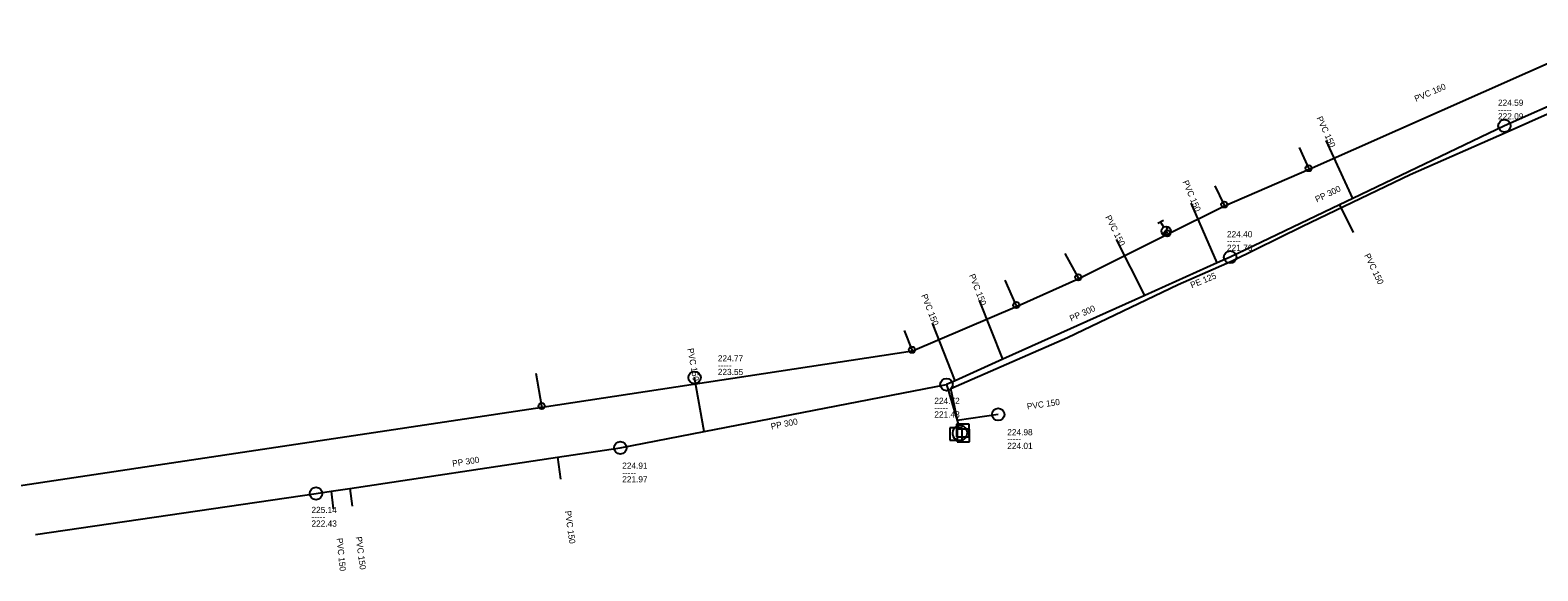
# Model space of a CAD drawing. Extents: x -770828 to -770111, y -1050344 to -1049447.
# Drawn here: x -770523.9 to -770280.9, y -1050344.4 to -1050257.2 of the extents above; entities that cross this region are included whole.
import ezdxf

# ---------------------------------------------------------------- set-up
doc = ezdxf.new("R2010")
doc.units = 0
doc.layers.add('Level 0', color=7, linetype='Continuous')

msp = doc.modelspace()

# ---------------------------------------------------------------- linework, layer by layer
at = {"layer": 'Level 0'}
for p, q in [((-770267.13, -1050257.23), (-770317.71, -1050279.72)), ((-770264.95, -1050263.2), (-770286.27, -1050272.66)), ((-770285.81, -1050273.65), (-770264.35, -1050264)), ((-770286.27, -1050272.66), (-770310.7, -1050284.36)), ((-770301.46, -1050280.51), (-770285.81, -1050273.65)), ((-770317.81, -1050279.5), (-770319.29, -1050276.15)), ((-770310.7, -1050284.36), (-770315.01, -1050275.04)), ((-770317.71, -1050279.72), (-770317.81, -1050279.5)), ((-770317.71, -1050279.72), (-770331.38, -1050285.6)), ((-770318.79, -1050288.84), (-770301.46, -1050280.51)), ((-770331.42, -1050285.36), (-770332.9, -1050282.35)), ((-770310.7, -1050284.36), (-770312.83, -1050285.38)), ((-770331.38, -1050285.6), (-770340.54, -1050290.17)), ((-770332.58, -1050294.78), (-770336.74, -1050285.12)), ((-770331.38, -1050285.6), (-770331.42, -1050285.36)), ((-770312.83, -1050285.38), (-770330.47, -1050293.83)), ((-770312.83, -1050285.38), (-770310.66, -1050289.87)), ((-770342.1, -1050288.37), (-770341.23, -1050287.87)), ((-770341.17, -1050288.99), (-770341.67, -1050288.12)), ((-770341.07, -1050290.33), (-770340.51, -1050288.94)), ((-770330.16, -1050294.43), (-770318.79, -1050288.84)), ((-770340.54, -1050290.17), (-770354.88, -1050297.33)), ((-770344.21, -1050300.01), (-770348.78, -1050291)), ((-770340.79, -1050289.64), (-770340.61, -1050290)), ((-770340.61, -1050290), (-770340.54, -1050290.17)), ((-770354.94, -1050297.09), (-770357.06, -1050293.23)), ((-770330.47, -1050293.83), (-770332.58, -1050294.78)), ((-770332.58, -1050294.78), (-770344.21, -1050300.01)), ((-770338.86, -1050298.24), (-770330.16, -1050294.43)), ((-770364.93, -1050301.57), (-770366.74, -1050297.55)), ((-770354.88, -1050297.33), (-770364.81, -1050301.79)), ((-770356.68, -1050306.8), (-770338.86, -1050298.24)), ((-770354.88, -1050297.33), (-770354.94, -1050297.09)), ((-770367.13, -1050310.32), (-770370.87, -1050300.82)), ((-770344.21, -1050300.01), (-770367.13, -1050310.32)), ((-770364.81, -1050301.79), (-770381.64, -1050309.03)), ((-770364.81, -1050301.79), (-770364.93, -1050301.57)), ((-770381.73, -1050308.79), (-770382.96, -1050305.65)), ((-770374.8, -1050313.77), (-770378.45, -1050304.48)), ((-770375.48, -1050315.03), (-770356.68, -1050306.8)), ((-770381.64, -1050309.03), (-770441.37, -1050318.11)), ((-770381.64, -1050309.03), (-770381.73, -1050308.79)), ((-770367.13, -1050310.32), (-770374.8, -1050313.77)), ((-770441.42, -1050317.86), (-770442.33, -1050312.6)), ((-770415.24, -1050321.98), (-770416.79, -1050313.27)), ((-770415.24, -1050321.98), (-770376.18, -1050314.39)), ((-770374.8, -1050313.77), (-770376.18, -1050314.39)), ((-770376.18, -1050314.39), (-770374.46, -1050320.17)), ((-770374.17, -1050321.15), (-770375.48, -1050315.03)), ((-770441.37, -1050318.11), (-770569.94, -1050337.38)), ((-770441.37, -1050318.11), (-770441.42, -1050317.86)), ((-770372.55, -1050320.8), (-770374.55, -1050320.8)), ((-770374.55, -1050320.8), (-770374.55, -1050322.8)), ((-770367.85, -1050319.2), (-770374.46, -1050320.17)), ((-770374.46, -1050320.17), (-770374.17, -1050321.15)), ((-770372.55, -1050322.8), (-770372.55, -1050320.8)), ((-770428.75, -1050324.6), (-770415.24, -1050321.98)), ((-770373.67, -1050321.37), (-770375.67, -1050321.37)), ((-770375.67, -1050321.37), (-770375.67, -1050323.37)), ((-770375.18, -1050321.84), (-770375.24, -1050322.15)), ((-770375.24, -1050322.15), (-770375.22, -1050322.46)), ((-770375.22, -1050322.46), (-770375.12, -1050322.75)), ((-770375.05, -1050321.56), (-770375.18, -1050321.84)), ((-770375.12, -1050322.75), (-770374.94, -1050323.01)), ((-770374.85, -1050321.33), (-770375.05, -1050321.56)), ((-770374.94, -1050323.01), (-770374.71, -1050323.22)), ((-770374.6, -1050321.15), (-770374.85, -1050321.33)), ((-770374.71, -1050323.22), (-770374.44, -1050323.36)), ((-770374.3, -1050321.04), (-770374.6, -1050321.15)), ((-770374.55, -1050322.8), (-770372.55, -1050322.8)), ((-770372.46, -1050321.61), (-770374.46, -1050321.61)), ((-770374.46, -1050321.61), (-770374.46, -1050323.61)), ((-770374, -1050321.01), (-770374.3, -1050321.04)), ((-770373.69, -1050321.06), (-770374, -1050321.01)), ((-770373.82, -1050323.41), (-770373.52, -1050323.32)), ((-770373.4, -1050321.18), (-770373.69, -1050321.06)), ((-770373.67, -1050323.37), (-770373.67, -1050321.37)), ((-770373.52, -1050323.32), (-770373.26, -1050323.16)), ((-770373.16, -1050321.37), (-770373.4, -1050321.18)), ((-770373.26, -1050323.16), (-770373.05, -1050322.93)), ((-770372.97, -1050321.62), (-770373.16, -1050321.37)), ((-770373.05, -1050322.93), (-770372.9, -1050322.66)), ((-770372.86, -1050321.91), (-770372.97, -1050321.62)), ((-770372.9, -1050322.66), (-770372.83, -1050322.35)), ((-770372.82, -1050322.22), (-770372.86, -1050321.91)), ((-770372.83, -1050322.35), (-770372.82, -1050322.22)), ((-770372.46, -1050323.61), (-770372.46, -1050321.61)), ((-770438.88, -1050326.12), (-770428.75, -1050324.6)), ((-770375.67, -1050323.37), (-770373.67, -1050323.37)), ((-770374.46, -1050323.61), (-770372.46, -1050323.61)), ((-770374.44, -1050323.36), (-770374.13, -1050323.43)), ((-770374.13, -1050323.43), (-770373.82, -1050323.41)), ((-770472.35, -1050331.14), (-770438.88, -1050326.12)), ((-770438.88, -1050326.12), (-770438.4, -1050329.67)), ((-770523.01, -1050338.56), (-770477.79, -1050331.96)), ((-770477.79, -1050331.96), (-770475.33, -1050331.59)), ((-770475.33, -1050331.59), (-770472.35, -1050331.14)), ((-770475.33, -1050331.59), (-770475.04, -1050334.42)), ((-770472.35, -1050331.14), (-770471.98, -1050334.02))]:
    msp.add_line(p, q, dxfattribs=at)
for centre, radius in [((-770286.27, -1050272.66), 1), ((-770317.81, -1050279.5), 0.5), ((-770331.42, -1050285.36), 0.5), ((-770340.79, -1050289.64), 0.75), ((-770340.61, -1050290), 0.5), ((-770330.47, -1050293.83), 1), ((-770354.94, -1050297.09), 0.5), ((-770364.93, -1050301.57), 0.5), ((-770381.73, -1050308.79), 0.5), ((-770416.79, -1050313.27), 1), ((-770376.18, -1050314.39), 1), ((-770441.42, -1050317.86), 0.5), ((-770367.85, -1050319.2), 1), ((-770428.75, -1050324.6), 1), ((-770477.79, -1050331.96), 1)]:
    msp.add_circle(centre, radius, dxfattribs=at)

# ---------------------------------------------------------------- texts
for s, rotation, p in [('PVC 160', 23.274, (-770300.51, -1050268.81)), ('PVC 150', 294.818, (-770316.58, -1050271.41)), ('PVC 150', 293.299, (-770338.17, -1050281.7)), ('PP 300', 25.589, (-770316.49, -1050285.04)), ('PVC 150', 296.895, (-770350.64, -1050287.39)), ('PVC 150', 295.794, (-770308.89, -1050293.55)), ('PVC 150', 291.489, (-770372.58, -1050296.78)), ('PE 125', 22.348, (-770336.64, -1050298.88)), ('PVC 150', 291.45, (-770380.28, -1050300.02)), ('PP 300', 24.219, (-770356.08, -1050304.25)), ('PVC 150', 280.091, (-770417.95, -1050308.62)), ('PVC 150', 8.348, (-770363.15, -1050318.43)), ('PP 300', 10.996, (-770404.4, -1050321.64)), ('PP 300', 8.53, (-770455.76, -1050327.64)), ('PVC 150', 277.7, (-770437.68, -1050334.81)), ('PVC 150', 275.851, (-770474.5, -1050339.19)), ('PVC 150', 277.321, (-770471.4, -1050338.98))]:
    msp.add_text(s, height=1, rotation=rotation, dxfattribs=at).set_placement(p)
for s, p in [('224.59', (-770287.3, -1050269.43)), ('-----', (-770287.3, -1050270.53)), ('222.09', (-770287.3, -1050271.63)), ('-----', (-770330.98, -1050291.74)), ('224.40', (-770330.98, -1050290.64)), ('221.76', (-770330.98, -1050292.84)), ('224.77', (-770413.04, -1050310.66)), ('-----', (-770413.04, -1050311.76)), ('223.55', (-770413.04, -1050312.86)), ('-----', (-770378.14, -1050318.61)), ('224.72', (-770378.14, -1050317.51)), ('221.48', (-770378.14, -1050319.71)), ('-----', (-770366.39, -1050323.68)), ('224.98', (-770366.39, -1050322.58)), ('224.01', (-770366.39, -1050324.78)), ('224.91', (-770428.45, -1050327.97)), ('-----', (-770428.45, -1050329.07)), ('221.97', (-770428.45, -1050330.17)), ('225.14', (-770478.53, -1050335.11)), ('-----', (-770478.53, -1050336.21)), ('222.43', (-770478.53, -1050337.31))]:
    msp.add_text(s, height=1, dxfattribs=at).set_placement(p)

doc.saveas('drawing.dxf')
